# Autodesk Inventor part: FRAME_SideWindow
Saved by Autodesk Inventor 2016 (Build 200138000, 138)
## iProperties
Created: 2016-03
Part Number: FRAME_SideWindow
Material: Generic
Document SubType Name: Modeling
Designer: bongo_000
Density: 1 g/cm^3
Appearance: Default
Author: bongo_000
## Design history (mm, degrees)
feature "SOLID1"
body "Solid1"
